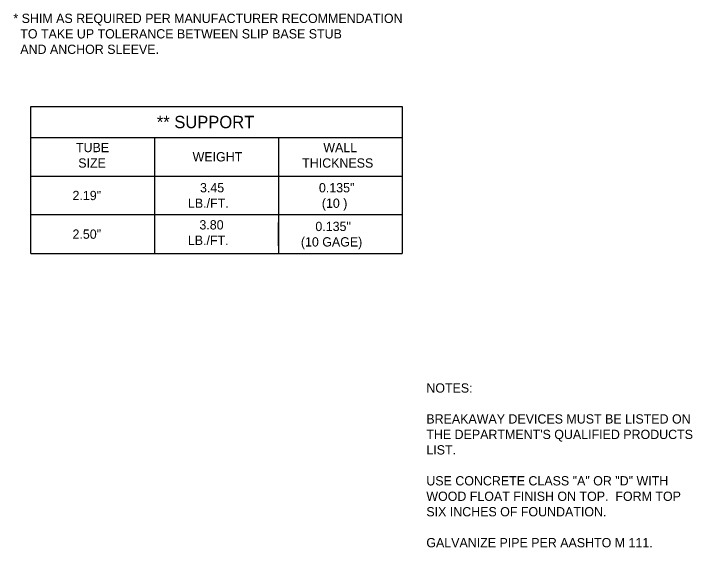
# Model space of a CAD drawing. Extents: x 49940 to 50043, y 49986 to 50011.
# Drawn here: x 49951.355 to 49955.741, y 49988.628 to 49992.08 of the extents above; entities that cross this region are included whole.
import ezdxf

# ---------------------------------------------------------------- set-up
doc = ezdxf.new("R2010")
doc.units = 0
doc.layers.add('Level 2', color=7, linetype='Continuous')

msp = doc.modelspace()

# ---------------------------------------------------------------- linework, layer by layer
at = {"layer": 'Level 2'}
for p, q in [((49951.4661, 49991.4787), (49953.8661, 49991.4787)), ((49951.4661, 49990.5287), (49951.4661, 49991.4787)), ((49953.8661, 49991.4787), (49953.8661, 49990.5287)), ((49951.4661, 49991.2787), (49953.8661, 49991.2787)), ((49952.2661, 49991.2787), (49952.2661, 49990.5287)), ((49953.0661, 49991.2787), (49953.0661, 49990.5287)), ((49951.4661, 49991.0287), (49953.8661, 49991.0287)), ((49952.2667, 49991.0283), (49952.2667, 49991.0283)), ((49953.0665, 49991.0283), (49953.0665, 49991.0283)), ((49953.0656, 49990.8786), (49953.0656, 49990.8786)), ((49953.0663, 49990.8791), (49953.0663, 49990.8791)), ((49953.8661, 49990.7787), (49951.4661, 49990.7787)), ((49952.2667, 49990.7787), (49952.2667, 49990.7787)), ((49953.0653, 49990.7787), (49953.0653, 49990.7787)), ((49953.0656, 49990.7283), (49953.0656, 49990.7283)), ((49953.0661, 49990.5787), (49953.0661, 49990.7283)), ((49953.066, 49990.5792), (49953.066, 49990.5792)), ((49953.0663, 49990.5792), (49953.0663, 49990.5792)), ((49951.4661, 49990.5287), (49953.8661, 49990.5287))]:
    msp.add_line(p, q, dxfattribs=at)

# ---------------------------------------------------------------- texts
for s, height, p in [('* SHIM AS REQUIRED PER MANUFACTURER RECOMMENDATION ', 0.06, (49951.3537, 49992.0188)), ('  TO TAKE UP TOLERANCE BETWEEN SLIP BASE STUB ', 0.06, (49951.3537, 49991.9188)), ('  AND ANCHOR SLEEVE.', 0.06, (49951.3537, 49991.8188)), ('** SUPPORT', 0.0799, (49952.2805, 49991.3387)), ('TUBE', 0.06, (49951.758, 49991.1836)), ('WALL', 0.06, (49953.3561, 49991.1836)), ('WEIGHT', 0.06, (49952.5116, 49991.1237)), ('SIZE', 0.06, (49951.7729, 49991.0836)), ('THICKNESS', 0.06, (49953.2196, 49991.0836)), ('3.45', 0.06, (49952.5593, 49990.9238)), ('0.135"', 0.06, (49953.3277, 49990.9237)), ('2.19"', 0.06, (49951.7358, 49990.8735)), ('LB./FT.', 0.06, (49952.4815, 49990.8238)), ('(10 )', 0.06, (49953.3465, 49990.8237)), ('3.80', 0.06, (49952.5557, 49990.6838)), ('0.135"', 0.06, (49953.3048, 49990.6737)), ('2.50"', 0.06, (49951.7358, 49990.6237)), ('LB./FT.', 0.06, (49952.4809, 49990.5838)), ('(10 GAGE)', 0.06, (49953.211, 49990.5737)), ('NOTES:', 0.06, (49954.0216, 49989.629)), ('BREAKAWAY DEVICES MUST BE LISTED ON', 0.06, (49954.0216, 49989.429)), ("THE DEPARTMENT'S QUALIFIED PRODUCTS  ", 0.06, (49954.0216, 49989.329)), ('LIST.', 0.06, (49954.0216, 49989.229)), ('USE CONCRETE CLASS "A" OR "D" WITH', 0.06, (49954.0216, 49989.029)), ('WOOD FLOAT FINISH ON TOP.  FORM TOP', 0.06, (49954.0216, 49988.929)), ('SIX INCHES OF FOUNDATION.', 0.06, (49954.0216, 49988.829)), ('GALVANIZE PIPE PER AASHTO M 111.', 0.06, (49954.0216, 49988.629))]:
    msp.add_text(s, height=height, dxfattribs=at).set_placement(p)

doc.saveas('drawing.dxf')
